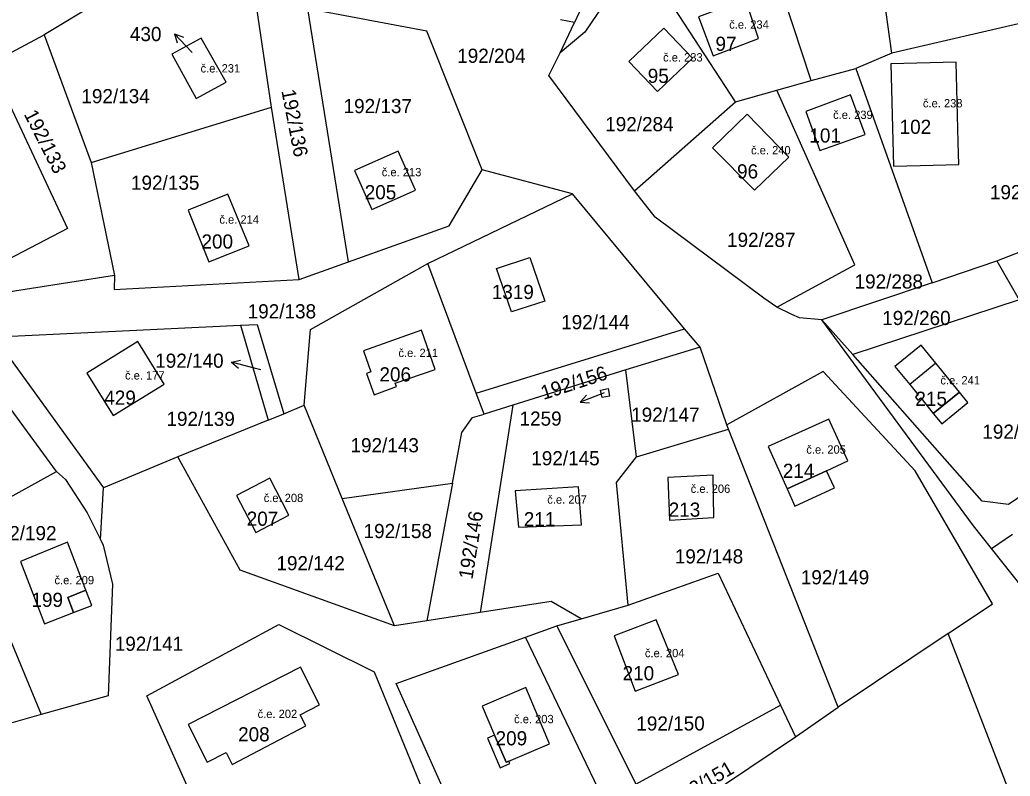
# Model space of a CAD drawing. Extents: x -887272 to -880188, y -1026687 to -1021896.
# Drawn here: x -882201.9 to -882082.9, y -1024194 to -1024103.2 of the extents above; entities that cross this region are included whole.
import ezdxf

# ---------------------------------------------------------------- set-up
doc = ezdxf.new("R2010")
doc.units = 0
for name, color, linetype in [('Definiční body', 7, 'Continuous'), ('Hranice parcel', 7, 'Continuous'), ('Parcelní čísla', 7, 'Continuous'), ('Polygon budovy', 7, 'Continuous'), ('Pop  PČ popisy', 7, 'Continuous'), ('Vnitřní kresba', 7, 'Continuous')]:
    doc.layers.add(name, color=color, linetype=linetype)

msp = doc.modelspace()

# ---------------------------------------------------------------- linework, layer by layer
at = {"layer": 'Hranice parcel'}
for p, q in [((-882125.39, -1024082.57), (-882135.22, -1024103.54)), ((-882106.8, -1024110.48), (-882110.89, -1024098.01)), ((-882171.6, -1024113.68), (-882173.55, -1024100.7)), ((-882162.36, -1024132.25), (-882167.27, -1024101.87)), ((-882136.92, -1024107.16), (-882135.22, -1024103.54)), ((-882135.22, -1024103.54), (-882136.89, -1024103.2)), ((-882079.4, -1024103.11), (-882097.11, -1024107.19)), ((-882205.42, -1024108.48), (-882198.92, -1024105.01)), ((-882198.92, -1024105.01), (-882193.28, -1024120.35)), ((-882097.11, -1024107.19), (-882101.42, -1024109.04)), ((-882106.8, -1024110.48), (-882101.42, -1024109.04)), ((-882101.42, -1024109.04), (-882092.24, -1024134.77)), ((-882110.9, -1024111.66), (-882106.8, -1024110.48)), ((-882115.87, -1024113.05), (-882110.9, -1024111.66)), ((-882127.99, -1024123.73), (-882115.87, -1024113.05)), ((-882193.28, -1024120.35), (-882171.6, -1024113.68)), ((-882168.3, -1024134.38), (-882171.6, -1024113.68)), ((-882114.47, -1024114.55), (-882118.63, -1024118.59)), ((-882193.28, -1024120.35), (-882190.49, -1024133.91)), ((-882135.46, -1024124.1), (-882146.33, -1024121.21)), ((-882152.85, -1024132.47), (-882135.46, -1024124.1)), ((-882121.99, -1024140.29), (-882135.46, -1024124.1)), ((-882125.54, -1024126.91), (-882127.99, -1024123.73)), ((-882084.49, -1024132.15), (-882072.69, -1024127.57)), ((-882168.3, -1024134.38), (-882162.36, -1024132.25)), ((-882147.02, -1024148.04), (-882152.85, -1024132.47)), ((-882092.24, -1024134.77), (-882084.49, -1024132.15)), ((-882084.49, -1024132.15), (-882081.79, -1024136.83)), ((-882190.49, -1024133.91), (-882208.64, -1024136.73)), ((-882092.24, -1024134.77), (-882105.5, -1024139.21)), ((-882081.79, -1024136.83), (-882101.79, -1024143.4)), ((-882105.5, -1024139.21), (-882108.17, -1024138.99)), ((-882101.79, -1024143.4), (-882105.5, -1024139.21)), ((-882204.92, -1024141.27), (-882175.35, -1024139.88)), ((-882175.35, -1024139.88), (-882172, -1024151.25)), ((-882147.02, -1024148.04), (-882121.99, -1024140.29)), ((-882120.13, -1024142.52), (-882121.99, -1024140.29)), ((-882204.92, -1024141.27), (-882191.8, -1024159.41)), ((-882197.43, -1024157.42), (-882208.75, -1024142.05)), ((-882120.13, -1024142.52), (-882129.04, -1024145.21)), ((-882116.93, -1024151.83), (-882120.13, -1024142.52)), ((-882129.04, -1024145.21), (-882142.63, -1024149.47)), ((-882127.78, -1024155.66), (-882129.04, -1024145.21)), ((-882146.08, -1024150.53), (-882147.02, -1024148.04)), ((-882170.15, -1024150.49), (-882167.7, -1024149.48)), ((-882163.11, -1024160.68), (-882167.7, -1024149.48)), ((-882142.63, -1024149.47), (-882146.55, -1024174.36)), ((-882142.63, -1024149.47), (-882146.08, -1024150.53)), ((-882172, -1024151.25), (-882182.86, -1024155.68)), ((-882172, -1024151.25), (-882170.15, -1024150.49)), ((-882104.65, -1024151.14), (-882111.97, -1024154.45)), ((-882127.78, -1024155.66), (-882116.73, -1024152.35)), ((-882116.73, -1024152.35), (-882116.93, -1024151.83)), ((-882182.86, -1024155.68), (-882191.8, -1024159.41)), ((-882208.53, -1024163.52), (-882197.43, -1024157.42)), ((-882192.18, -1024165.6), (-882191.8, -1024159.41)), ((-882163.11, -1024160.68), (-882149.88, -1024158.85)), ((-882149.88, -1024158.85), (-882152.96, -1024175.37)), ((-882156.86, -1024175.96), (-882163.11, -1024160.68)), ((-882208.46, -1024164.48), (-882199.3, -1024186.6)), ((-882085.12, -1024166.68), (-882082.59, -1024164.97)), ((-882075.46, -1024178.88), (-882085.12, -1024166.68)), ((-882134.42, -1024175.12), (-882128.79, -1024173.47)), ((-882090.34, -1024176.88), (-882085.01, -1024173.3)), ((-882146.55, -1024174.36), (-882152.96, -1024175.37)), ((-882137.35, -1024175.98), (-882134.42, -1024175.12)), ((-882152.96, -1024175.37), (-882156.86, -1024175.96)), ((-882141.11, -1024177.32), (-882137.35, -1024175.98)), ((-882137.35, -1024175.98), (-882127.83, -1024194.96)), ((-882090.34, -1024176.88), (-882103.55, -1024185.73)), ((-882083.16, -1024195.4), (-882090.34, -1024176.88)), ((-882127.83, -1024194.96), (-882110.47, -1024185.49)), ((-882110.47, -1024185.49), (-882108.68, -1024189.29)), ((-882108.68, -1024189.29), (-882103.55, -1024185.73)), ((-882125.14, -1024200.32), (-882108.68, -1024189.29))]:
    msp.add_line(p, q, dxfattribs=at)
for points in [[(-882097.11, -1024107.19), (-882098.95, -1024093.95), (-882097.56, -1024087.36), (-882098.57, -1024080.99), (-882098.08, -1024072.99)], [(-882115.87, -1024113.05), (-882127.53, -1024095.15), (-882133.96, -1024104.67), (-882136.92, -1024107.16)], [(-882173.55, -1024100.7), (-882186.69, -1024097.6), (-882198.92, -1024105.01)], [(-882120.33, -1024102.86), (-882118.57, -1024107.51), (-882113.1, -1024105.46), (-882114.69, -1024100.73), (-882120.33, -1024102.86)], [(-882146.33, -1024121.21), (-882152.94, -1024104.55), (-882167.27, -1024101.87)], [(-882124.49, -1024104.19), (-882128.69, -1024108.19), (-882125.24, -1024111.81), (-882121.04, -1024107.8), (-882124.49, -1024104.19)], [(-882183.61, -1024107.32), (-882180.65, -1024112.65), (-882177.07, -1024110.69), (-882180.05, -1024105.39), (-882183.61, -1024107.32)], [(-882127.99, -1024123.73), (-882138.29, -1024109.91), (-882136.92, -1024107.16)], [(-882205.42, -1024108.48), (-882196.11, -1024128.27), (-882209.58, -1024135.28)], [(-882096.91, -1024120.77), (-882093.7, -1024120.7), (-882089.06, -1024120.58), (-882089.12, -1024117.91), (-882089.36, -1024108.28), (-882097.2, -1024108.5), (-882096.91, -1024120.77)], [(-882110.9, -1024137.72), (-882101.52, -1024132.63), (-882110.9, -1024111.66)], [(-882102.06, -1024112.22), (-882107.42, -1024114.2), (-882105.74, -1024118.88), (-882100.3, -1024116.96), (-882102.06, -1024112.22)], [(-882118.63, -1024118.59), (-882113.58, -1024123.66), (-882109.48, -1024119.68), (-882114.47, -1024114.55)], [(-882154.32, -1024123.65), (-882156.42, -1024118.97), (-882161.65, -1024121.31), (-882159.55, -1024125.99), (-882154.32, -1024123.65)], [(-882162.36, -1024132.25), (-882150.29, -1024127.92), (-882146.33, -1024121.21)], [(-882181.64, -1024126.04), (-882179.14, -1024132.28), (-882174.3, -1024130.34), (-882176.86, -1024124.14), (-882181.64, -1024126.04)], [(-882110.9, -1024137.72), (-882112.46, -1024136.61), (-882125.54, -1024126.91)], [(-882167.7, -1024149.48), (-882166.92, -1024140.37), (-882152.85, -1024132.47)], [(-882138.78, -1024137), (-882142.8, -1024138.26), (-882144.6, -1024133.06), (-882140.6, -1024131.76), (-882138.78, -1024137)], [(-882190.49, -1024133.91), (-882190.51, -1024135.59), (-882168.3, -1024134.38)], [(-882108.17, -1024138.99), (-882109.1, -1024138.6), (-882110.9, -1024137.72)], [(-882085.12, -1024166.68), (-882087.28, -1024163.96), (-882105.5, -1024139.21)], [(-882175.35, -1024139.88), (-882173.36, -1024139.79), (-882170.15, -1024150.49)], [(-882153.61, -1024140.47), (-882160.58, -1024142.94), (-882159.68, -1024145.48), (-882160.2, -1024145.66), (-882159.3, -1024148.21), (-882156.62, -1024147.24), (-882156.77, -1024146.81), (-882151.94, -1024145.18), (-882153.61, -1024140.47)], [(-882190.66, -1024150.72), (-882184.53, -1024146.93), (-882187.69, -1024141.82), (-882193.82, -1024145.61), (-882190.66, -1024150.72)], [(-882088.97, -1024147.9), (-882091.81, -1024144.42), (-882093.58, -1024142.25), (-882096.72, -1024144.81), (-882094.95, -1024146.98), (-882093.93, -1024148.24), (-882094.27, -1024148.51), (-882093.97, -1024148.88), (-882093.63, -1024148.6), (-882092.11, -1024150.46), (-882091.1, -1024151.7), (-882087.96, -1024149.14), (-882088.97, -1024147.9)], [(-882071.96, -1024153.83), (-882083.08, -1024161.39), (-882086.23, -1024160.99), (-882101.79, -1024143.4)], [(-882085.01, -1024173.3), (-882094.28, -1024157.36), (-882105.36, -1024145.41), (-882116.93, -1024151.83)], [(-882132.08, -1024147.65), (-882131.18, -1024147.47), (-882131.01, -1024148.38), (-882131.91, -1024148.55), (-882132.08, -1024147.65)], [(-882149.88, -1024158.85), (-882148.74, -1024152.76), (-882147.46, -1024150.96), (-882146.08, -1024150.53)], [(-882111.97, -1024154.45), (-882109.67, -1024159.53), (-882108.74, -1024161.59), (-882103.98, -1024159.4), (-882104.93, -1024157.35), (-882102.37, -1024156.17), (-882104.65, -1024151.14)], [(-882103.55, -1024185.73), (-882105.38, -1024181.09), (-882116.73, -1024152.35)], [(-882156.86, -1024175.96), (-882175.4, -1024169.27), (-882182.86, -1024155.68)], [(-882128.79, -1024173.47), (-882130.17, -1024158.74), (-882127.78, -1024155.66)], [(-882197.43, -1024157.42), (-882196.38, -1024158.38), (-882193.75, -1024162.38), (-882192.18, -1024165.6)], [(-882171.81, -1024158.23), (-882175.81, -1024160.3), (-882173.52, -1024164.74), (-882169.52, -1024162.68), (-882171.81, -1024158.23)], [(-882123.82, -1024163.26), (-882118.46, -1024162.96), (-882118.57, -1024157.86), (-882124, -1024158.16), (-882123.82, -1024163.26)], [(-882134.38, -1024163.82), (-882134.74, -1024159.28), (-882142.36, -1024159.74), (-882141.96, -1024164.1), (-882134.38, -1024163.82)], [(-882192.18, -1024165.6), (-882191.86, -1024166.27), (-882190.73, -1024170.94), (-882191.25, -1024184.38), (-882199.3, -1024186.6)], [(-882193.91, -1024171.67), (-882196.13, -1024165.91), (-882201.76, -1024168.25), (-882198.89, -1024175.72), (-882195.39, -1024174.36), (-882193.2, -1024173.51), (-882193.91, -1024171.67)], [(-882128.79, -1024173.47), (-882117.94, -1024169.64), (-882110.47, -1024185.49)], [(-882199.3, -1024186.6), (-882203.76, -1024187.9), (-882224.27, -1024172.09), (-882225.84, -1024171.07)], [(-882134.42, -1024175.12), (-882138.03, -1024173.03), (-882146.55, -1024174.36)], [(-882122.72, -1024181.82), (-882125.42, -1024175.24), (-882130.45, -1024177.16), (-882127.94, -1024183.8), (-882122.72, -1024181.82)], [(-882180.08, -1024198.94), (-882186.61, -1024184.38), (-882170.75, -1024175.81), (-882159.27, -1024181.5), (-882149.19, -1024206.14)], [(-882145.92, -1024206.9), (-882156.65, -1024182.88), (-882141.11, -1024177.32)], [(-882145.92, -1024206.9), (-882131.84, -1024196.57), (-882141.11, -1024177.32)], [(-882177.07, -1024191.18), (-882176.34, -1024192.6), (-882167.48, -1024187.96), (-882168.16, -1024186.63), (-882165.84, -1024185.45), (-882168.13, -1024180.94), (-882181.64, -1024187.81), (-882179.34, -1024192.33), (-882177.07, -1024191.18)], [(-882144.14, -1024192.99), (-882142.99, -1024192.5), (-882143.12, -1024192.2), (-882138.23, -1024190.14), (-882141.08, -1024183.38), (-882146.31, -1024185.62), (-882144.82, -1024189.09), (-882145.66, -1024189.45), (-882144.14, -1024192.99)]]:
    msp.add_lwpolyline(points, dxfattribs=at)
at = {"layer": 'Polygon budovy'}
for points in [[(-882120.33, -1024102.86), (-882118.57, -1024107.51), (-882113.1, -1024105.46), (-882114.69, -1024100.73)], [(-882128.69, -1024108.19), (-882125.24, -1024111.81), (-882121.04, -1024107.8), (-882124.49, -1024104.19)], [(-882180.05, -1024105.39), (-882183.61, -1024107.32), (-882180.65, -1024112.65), (-882177.07, -1024110.69)], [(-882097.2, -1024108.5), (-882096.91, -1024120.77), (-882093.7, -1024120.7), (-882089.06, -1024120.58), (-882089.12, -1024117.91), (-882089.36, -1024108.28)], [(-882107.42, -1024114.2), (-882105.74, -1024118.88), (-882100.3, -1024116.96), (-882102.06, -1024112.22)], [(-882114.47, -1024114.55), (-882118.63, -1024118.59), (-882113.58, -1024123.66), (-882109.48, -1024119.68)], [(-882161.65, -1024121.31), (-882159.55, -1024125.99), (-882154.32, -1024123.65), (-882156.42, -1024118.97)], [(-882181.64, -1024126.04), (-882179.14, -1024132.28), (-882174.3, -1024130.34), (-882176.86, -1024124.14)], [(-882160.58, -1024142.94), (-882159.68, -1024145.48), (-882160.2, -1024145.66), (-882159.3, -1024148.21), (-882156.62, -1024147.24), (-882156.77, -1024146.81), (-882151.94, -1024145.18), (-882153.61, -1024140.47)], [(-882193.82, -1024145.61), (-882190.66, -1024150.72), (-882184.53, -1024146.93), (-882187.69, -1024141.82)], [(-882091.81, -1024144.42), (-882094.95, -1024146.98), (-882093.93, -1024148.24), (-882094.27, -1024148.51), (-882093.97, -1024148.88), (-882093.63, -1024148.6), (-882092.11, -1024150.46), (-882088.97, -1024147.9)], [(-882104.65, -1024151.14), (-882111.97, -1024154.45), (-882109.67, -1024159.53), (-882104.93, -1024157.35), (-882102.37, -1024156.17)], [(-882173.52, -1024164.74), (-882169.52, -1024162.68), (-882171.81, -1024158.23), (-882175.81, -1024160.3)], [(-882118.46, -1024162.96), (-882118.57, -1024157.86), (-882124, -1024158.16), (-882123.82, -1024163.26)], [(-882142.36, -1024159.74), (-882141.96, -1024164.1), (-882134.38, -1024163.82), (-882134.74, -1024159.28)], [(-882196.13, -1024165.91), (-882201.76, -1024168.25), (-882198.89, -1024175.72), (-882195.39, -1024174.36), (-882196.09, -1024172.54), (-882193.91, -1024171.67)], [(-882122.72, -1024181.82), (-882125.42, -1024175.24), (-882130.45, -1024177.16), (-882127.94, -1024183.8)], [(-882179.34, -1024192.33), (-882177.07, -1024191.18), (-882176.34, -1024192.6), (-882167.48, -1024187.96), (-882168.16, -1024186.63), (-882165.84, -1024185.45), (-882168.13, -1024180.94), (-882181.64, -1024187.81)], [(-882141.08, -1024183.38), (-882146.31, -1024185.62), (-882144.82, -1024189.09), (-882143.42, -1024192.33), (-882143.12, -1024192.2), (-882138.23, -1024190.14)]]:
    msp.add_lwpolyline(points, close=True, dxfattribs=at)
at = {"layer": 'Pop  PČ popisy'}
for p, q in [((-882181.21, -1024107.09), (-882183.26, -1024104.9)), ((-882183.26, -1024104.9), (-882182.21, -1024105.29)), ((-882183.26, -1024104.9), (-882182.94, -1024105.97)), ((-882181.16, -1024107.14), (-882181.21, -1024107.09)), ((-882176.43, -1024144.29), (-882175.33, -1024144.07)), ((-882173.53, -1024145.07), (-882176.43, -1024144.29)), ((-882176.43, -1024144.29), (-882175.59, -1024145.04)), ((-882172.9, -1024145.24), (-882173.53, -1024145.07)), ((-882131.73, -1024148.01), (-882134.53, -1024149.09)), ((-882134.53, -1024149.09), (-882133.78, -1024148.26)), ((-882134.53, -1024149.09), (-882133.42, -1024149.19)), ((-882131.66, -1024147.99), (-882131.73, -1024148.01))]:
    msp.add_line(p, q, dxfattribs=at)
at = {"layer": 'Vnitřní kresba'}
for p, q in [((-882091.81, -1024144.42), (-882094.95, -1024146.98)), ((-882088.97, -1024147.9), (-882092.11, -1024150.46)), ((-882104.93, -1024157.35), (-882109.67, -1024159.53)), ((-882193.91, -1024171.67), (-882196.09, -1024172.54)), ((-882196.09, -1024172.54), (-882195.39, -1024174.36)), ((-882143.42, -1024192.33), (-882144.82, -1024189.09)), ((-882143.12, -1024192.2), (-882143.42, -1024192.33))]:
    msp.add_line(p, q, dxfattribs=at)

# ---------------------------------------------------------------- texts
at = {"layer": 'Definiční body'}
for s, p in [('č.e. 234', (-882116.63, -1024104.27)), ('č.e. 233', (-882124.58, -1024108.21)), ('č.e. 231', (-882180.14, -1024109.53)), ('č.e. 238', (-882093.36, -1024113.72)), ('č.e. 239', (-882104.15, -1024115.11)), ('č.e. 240', (-882114.01, -1024119.36)), ('č.e. 213', (-882158.37, -1024121.99)), ('č.e. 214', (-882177.88, -1024127.68)), ('č.e. 211', (-882156.37, -1024143.69)), ('č.e. 177', (-882189.22, -1024146.39)), ('č.e. 241', (-882091.26, -1024146.98)), ('č.e. 205', (-882107.37, -1024155.29)), ('č.e. 206', (-882121.26, -1024160)), ('č.e. 208', (-882172.56, -1024161.1)), ('č.e. 207', (-882138.49, -1024161.3)), ('č.e. 209', (-882197.69, -1024170.97)), ('č.e. 204', (-882126.76, -1024179.73)), ('č.e. 202', (-882173.29, -1024187.03)), ('č.e. 203', (-882142.48, -1024187.65))]:
    msp.add_text(s, height=1, dxfattribs=at).set_placement(p)
at = {"layer": 'Parcelní čísla'}
for s, p in [('430', (-882188.63, -1024105.76)), ('97', (-882118.28, -1024106.93)), ('192/204', (-882149.31, -1024108.37)), ('95', (-882126.42, -1024110.78)), ('192/134', (-882194.46, -1024113.22)), ('192/137', (-882162.96, -1024114.41)), ('192/284', (-882131.53, -1024116.58)), ('102', (-882096.16, -1024116.9)), ('101', (-882107, -1024117.94)), ('96', (-882115.69, -1024122.25)), ('192/135', (-882188.5, -1024123.61)), ('192/3', (-882085.31, -1024124.75)), ('205', (-882160.42, -1024124.75)), ('200', (-882180.03, -1024130.67)), ('192/287', (-882116.89, -1024130.47)), ('192/288', (-882101.57, -1024135.47)), ('1319', (-882145.16, -1024136.73)), ('192/138', (-882174.48, -1024139.05)), ('192/260', (-882098.25, -1024139.85)), ('192/144', (-882136.82, -1024140.35)), ('192/140', (-882185.59, -1024144.98)), ('206', (-882158.65, -1024146.62)), ('429', (-882191.71, -1024149.42)), ('215', (-882094.27, -1024149.55)), ('192/139', (-882184.24, -1024151.96)), ('1259', (-882141.82, -1024151.93)), ('192/147', (-882128.41, -1024151.46)), ('192/259', (-882086.22, -1024153.5)), ('192/143', (-882162.13, -1024155.13)), ('192/145', (-882140.41, -1024156.69)), ('214', (-882110.19, -1024158.2)), ('207', (-882174.6, -1024163.95)), ('213', (-882123.9, -1024162.86)), ('211', (-882141.31, -1024164.01)), ('192/192', (-882205.66, -1024165.68)), ('192/158', (-882160.56, -1024165.43)), ('192/148', (-882123.17, -1024168.47)), ('192/142', (-882171.03, -1024169.29)), ('192/149', (-882108.03, -1024170.98)), ('199', (-882200.46, -1024173.69)), ('192/141', (-882190.45, -1024178.96)), ('210', (-882129.44, -1024182.5)), ('192/150', (-882127.79, -1024188.53)), ('208', (-882175.63, -1024189.83)), ('209', (-882144.7, -1024190.31))]:
    msp.add_text(s, height=1.7, dxfattribs=at).set_placement(p)
for s, rotation, p in [('192/136', 281, (-882170.44, -1024111.72)), ('192/133', 297, (-882201.41, -1024114.52)), ('192/156', 18, (-882138.94, -1024148.85)), ('192/146', 81, (-882147.48, -1024170.44)), ('192/151', 30, (-882123.01, -1024197.67))]:
    msp.add_text(s, height=1.7, rotation=rotation, dxfattribs=at).set_placement(p)

doc.saveas('drawing.dxf')
